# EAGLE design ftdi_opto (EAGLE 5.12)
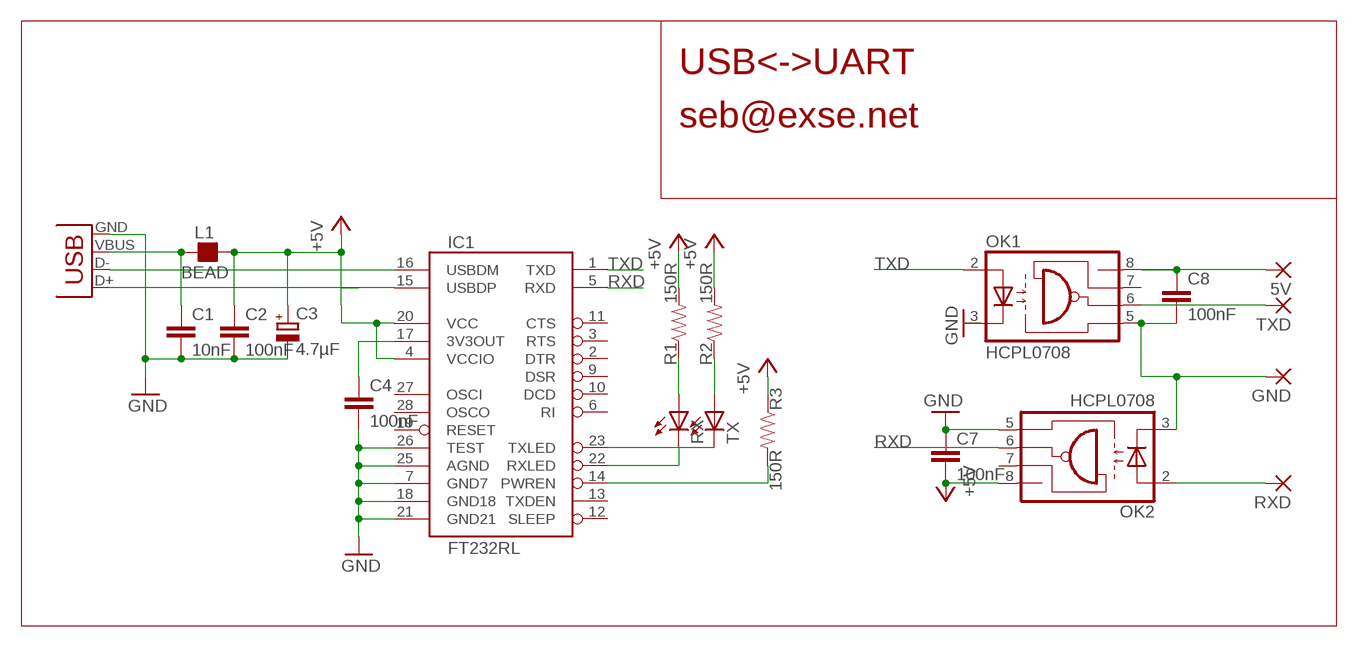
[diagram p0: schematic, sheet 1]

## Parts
5V  SMD2  [SMD1,27-2,54]
C1  10nF  CAP0805  [0805]
C2  100nF  CAP0805  [0805]
C3  4.7µF  CPOL-EUSMCC  [SMC_C]
C4  100nF  CAP0805  [0805]
C7  100nF  CAP0805  [0805]
C8  100nF  CAP0805  [0805]
GND  SMD2  [SMD1,27-2,54]
IC1  FT232RL  FT232RLSSOP  [SSOP28DB]
L1  BEAD  FB_0805  [L0805]
OK1  HCPL0708  HCPL0601  [SOIC08]
OK2  HCPL0708  HCPL0601  [SOIC08]
R1  150R  RESISTOR  [0805]
R2  150R  RESISTOR  [0805]
R3  150R  RESISTOR  [0805]
RX  LEDCHIP-LED0805  [CHIP-LED0805]
RXD  SMD2  [SMD1,27-2,54]
TX  LEDCHIP-LED0805  [CHIP-LED0805]
TXD  SMD2  [SMD1,27-2,54]
X1  USB-SMD-NS  [USB-MINIB-NOSTOP]

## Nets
+5V: C2.1 C3.+ C7.2 IC1.4(VCCIO) IC1.20(VCC) L1.2 OK2.8(VCC) R1.2 R2.2 R3.1
GND: C1.2 C2.2 C3.- C4.2 C7.1 IC1.7(GND7) IC1.18(GND18) IC1.21(GND21) IC1.25(AGND) IC1.26(TEST) OK1.3(C) OK2.5(GND) X1.GND
N$1: IC1.16(USBDM) X1.D-
N$2: IC1.15(USBDP) X1.D+
N$4: C1.1 L1.1 X1.VBUS
N$5: IC1.14(PWREN) R3.2
N$8: C8.2 GND.1(P) OK1.5(GND) OK2.3(C)
N$9: 5V.1(P) C8.1 OK1.8(VCC)
N$10: OK1.6(VO) TXD.1(P)
N$11: OK2.2(A) RXD.1(P)
N$19: R1.1 RX.A
N$20: R2.1 TX.A
N$27: IC1.22(RXLED) RX.C
N$28: IC1.23(TXLED) TX.C
N$29: C4.1 IC1.17(3V3OUT)
RXD: IC1.5(RXD) OK2.6(VO)
TXD: IC1.1(TXD) OK1.2(A)
Unconnected: IC1.2(DTR) IC1.3(RTS) IC1.6(RI) IC1.9(DSR) IC1.10(DCD) IC1.11(CTS) IC1.12(SLEEP) IC1.13(TXDEN) IC1.19(RESET) IC1.27(OSCI) IC1.28(OSCO) OK1.7(VE) OK2.7(VE)

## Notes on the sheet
- USB<->UART
- seb@exse.net

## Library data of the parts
5V GND RXD TXD = wirepad:SMD2: SMD PAD
C1 C2 C4 C7 C8 = SparkFun:CAP: Capacitor
C3 = resistor:CPOL-EU: POLARIZED CAPACITOR, European symbol
IC1 = SparkFun:FT232RL: USB UART FT232RL 4th Generation USB UART (USB <-> Serial) Controller. Spark Fun Electronics SKU : COM-00650
L1 = rc-master-smd:FB_: FERRITE BEAD
OK1 OK2 = optocoupler:HCPL0601: HEWLETT PACKARD OPTO COUPLER; MF: AGILENT TECHNOLOGIES; MPN: HCPL-0601-000E; OC_FARNELL: 9995102; OC_NEWARK: 88H7776
R1-R3 = SparkFun:RESISTOR: Resistor
RX TX = led:LED: LED
X1 = SparkFun:USB: USB Connectors USB-B-PTH is fully proven SKU : PRT-00139 USB-miniB is fully proven SKU : PRT-00587 USB-A-PCB is untested. USB-A-H is throughly reviewed, but untested. Spark Fun Electronics SKU : PRT-00437 USB-B-SMT is throughly reviewed, but untested. Needs silkscreen touching up. USB-A-S has not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

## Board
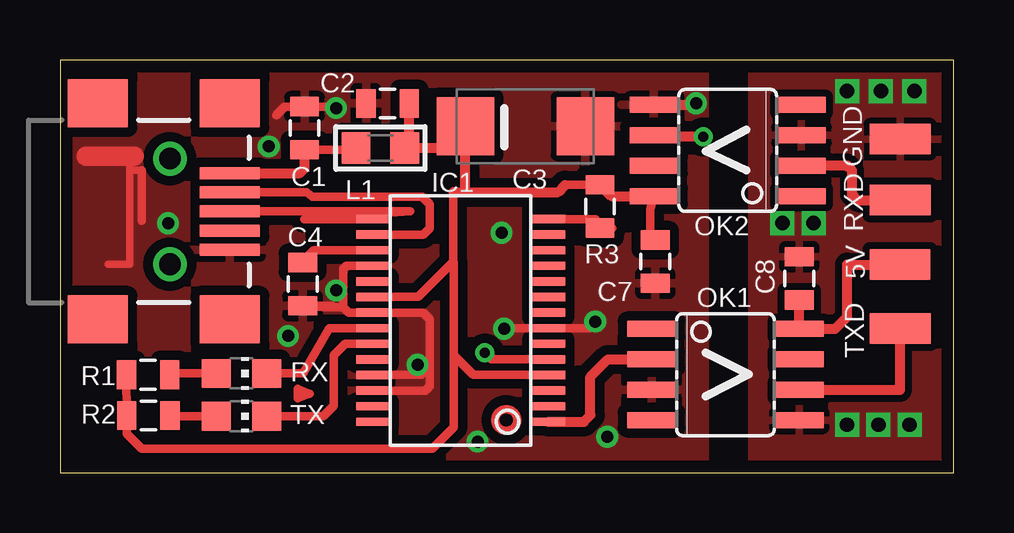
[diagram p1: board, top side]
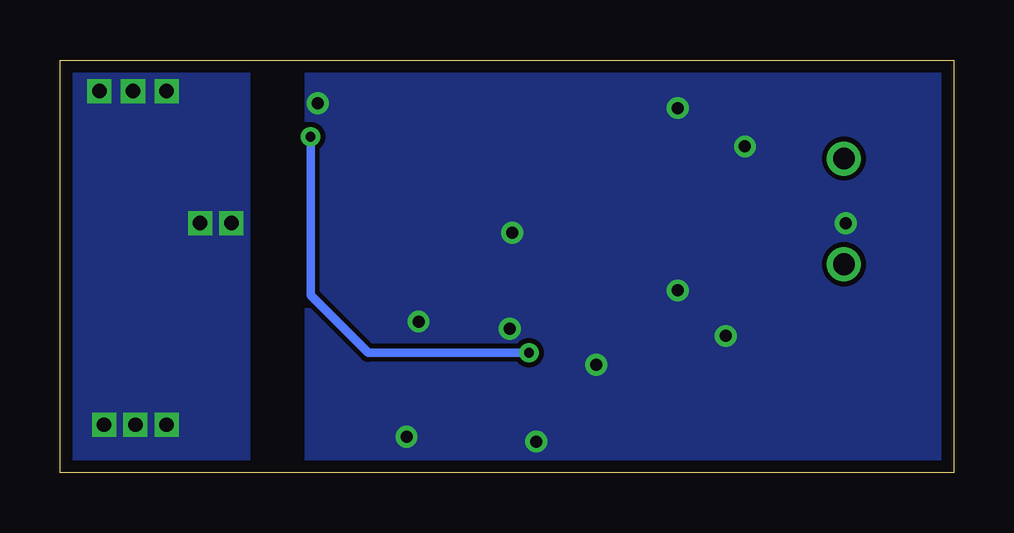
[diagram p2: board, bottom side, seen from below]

Size 37.24 x 17.2 mm. Coordinates in mm from the lower left corner, seen from the top.
Outline: 0,0 37.24,0 37.24,17.2 0,17.2 0,0
Copper layers (1*16): Top 0.035mm / dielectric 1.5mm / Bottom 0.035mm
Design rules "default *": minimum track width 10mil, minimum drill 0.3mm, track to track 8mil, track to pad 8mil, pad to pad 8mil, via to via 8mil, smd to smd 8mil, copper to edge 20mil, drill to drill 8mil, minimum pad ring 10mil, minimum via ring 8mil, stop-mask expansion 4mil, vias tented up to drill 50mil, thermal gap 10mil
tRestrict: 1 lines

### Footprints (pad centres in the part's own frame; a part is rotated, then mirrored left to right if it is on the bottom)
SMD1,27-2,54 = smd 1.27 x 2.54: 1 0,0
0805 = smd 0.8 x 1.2: 1 -0.9,0; 2 0.9,0
SMC_C = smd 2.4 x 2.4: + -2.5,0; - 2.5,0
SSOP28DB = smd 0.348 x 1.397: 1 -4.225,-3.656; 2 -3.575,-3.656; 3 -2.925,-3.656; 4 -2.275,-3.656; 5 -1.625,-3.656; 6 -0.975,-3.656; 7 -0.325,-3.656; 8 0.325,-3.656; 9 0.975,-3.656; 10 1.625,-3.656; 11 2.275,-3.656; 12 2.925,-3.656; 13 3.575,-3.656; 14 4.225,-3.656; 15 4.225,3.656; 16 3.575,3.656; 17 2.925,3.656; 18 2.275,3.656; 19 1.625,3.656; 20 0.975,3.656; 21 0.325,3.656; 22 -0.325,3.656; 23 -0.975,3.656; 24 -1.625,3.656; 25 -2.275,3.656; 26 -2.925,3.656; 27 -3.575,3.656; 28 -4.225,3.656
L0805 = smd 1.2 x 1.3: 1 -1.016,0; 2 1.016,0
SOIC08 = smd 0.66 x 2.032: 1 -1.905,-3.073; 2 -0.635,-3.073; 3 0.635,-3.073; 4 1.905,-3.073; 5 1.905,3.073; 6 0.635,3.073; 7 -0.635,3.073; 8 -1.905,3.073
CHIP-LED0805 = smd 1.2 x 1.2: A 0,-1.05; C 0,1.05
USB-MINIB-NOSTOP = smd 2.5 x 0.5: D+ 2.5,0; D- 2.5,0.8; GND 2.5,-1.6; ID 2.5,-0.8; VBUS 2.5,1.6 | smd 2.5 x 2: G1 -3,-4.5; G2 -3,4.5; G3 2.5,4.5; G4 2.5,-4.5 | drill 0.9 pad 0.8 round: H1 0,2.2 | drill 0.9 pad 0.787 round: H2 0,-2.2

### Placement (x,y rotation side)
5V  35,8.67 90 top
C1  10.19,14.36 90 top
C2  13.65,15.39 180 top
C3  19.39,14.44 0 top
C4  10.11,7.86 270 top
C7  24.8,8.8 90 top
C8  30.8,8.1 90 top
GND  35.01,13.9 90 top
IC1  16.69,6.35 90 top
L1  13.35,13.53 0 top
OK1  27.72,4.09 270 top
OK2  27.82,13.43 90 top
R1  3.67,4.09 180 top
R2  3.68,2.39 180 top
R3  22.5,11.1 270 top
RX  7.56,4.14 270 top
RXD  35,11.36 90 top
TX  7.56,2.36 270 top
TXD  35,6.01 90 top
X1  4.58,10.89 0 top

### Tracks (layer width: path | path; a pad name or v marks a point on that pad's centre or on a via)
+5V
  Top 0.35: IC1.20 14.93,7.33 16.39,8.79 | R1.2 R2.2 2.78,1.62 3.4,1 15.5,1 16.4,1.9 | 16.4,1.9 16.39,1.91 | 16.39,8.79 16.39,11.7 | 21.05,12 R3.1 | IC1.4 17.23,4.08 16.4,4.9 | 16.4,4.9 16.4,8.78 16.39,8.79 | 16.4,1.9 16.4,4.9 | OK2.8 24.6,10.98 24.6,9.9 24.6,9.7 C7.2
  Top 0.406: 21.05,12 20.75,11.7 16.9,11.7 | 16.39,11.7 16.9,11.7 | OK2.8 22.97,11.53 R3.1 | C2.1 14.55,13.71 L1.2 16.89,13.53 | 16.89,13.53 C3.+ | 16.89,13.53 16.89,11.7 16.9,11.7
GND  (via drill 0.5)
  Top 0.305: 2.9,12.6 3.4,12.6 | 2.9,12.6 2.9,13.2 | 2,8.7 2.9,8.7 2.9,12.6
  Top 0.35: IC1.26 15.22,3.43 15.4,3.6 15.4,4.4 | 15.4,4.4 15.4,6.4 15.12,6.68 IC1.21 12.03,6.68 11.8,6.9 | IC1.25 15.07,4.08 15.4,4.4 | 11.8,6.9 11.8,8.5 11.93,8.62 IC1.18 | 11.8,6.9 10.97,6.9 C4.2 11.34,6.96 | 11.36,15.26 C1.2 9.36,15.26 9,14.9 | 3.4,12.6 3.4,10.5 | 20.23,6.03 18.52,6.03 v18.5,6 | 20.23,6.03 IC1.7 | 20.23,6.03 22.05,6.03
  Top 0.406: OK2.5 26.34,15.34 v26.5,15.4
  Top 0.813: 1.1,13.2 2.9,13.2 3.1,13.2
  other vias: 9.5,5.7 11.5,7.6 14.9,4.5 18.4,10 11.5,15.2 8.7,13.6 4.5,10.4 22.8,1.5 22.3,6.3 17.4,1.3
  pour Top (isolate 0.4): 0,0 26.86,0.2 26.86,17.4 0,17.2
  pour Bottom: 26.88,17.4 0,17.2 0,0 26.88,0.2
N$1
  Top 0.35: IC1.16 15.12,9.93 15.4,10.2 15.4,11.2 15.1,11.5 10.5,11.5 10.29,11.69 X1.D-
N$2
  Top 0.35: X1.D+ 14.59,10.89 10.18,10.57 IC1.15
N$3
  Top 0.35: 9.9,3.5 9.9,3.1 10.4,3.3 9.9,3.5
N$4
  Top 0.35: C1.1 12.36,13.46 L1.1
  Top 0.406: X1.VBUS 9.99,12.49 10.19,12.69 C1.1 | L1.1 12.33,13.43
N$5
  Top 0.35: IC1.14 22.32,10.57 R3.2 23,10.2
N$8  (via drill 0.6)
  other vias: 30.1,10.4 31.4,10.4 34.1,2 34.2,15.9 32.8,2 35.4,2 32.8,15.9 35.6,15.9
  pour Bottom: 29.53,0.23 37.45,0.03 37.45,17.3 29.53,17.5
  pour Top (isolate 0.3): 28.83,0.03 37.45,0.03 37.45,17.3 28.83,17.3
N$9
  Top 0.35: OK1.8
  Top 0.406: OK1.8 C8.1 | 5V.1 32.8,8.67 32.8,6.5 32.3,6 OK1.8
N$10
  Top 0.406: TXD.1 35,3.46 OK1.6
N$11
  Top 0.406: OK2.2 32.8,12.8 33,12.6 33,11.6 33.24,11.36 RXD.1
N$19
  Top 0.35: R1.1 4.72,4.14 RX.A
N$20
  Top 0.35: R2.1 4.71,2.36 TX.A
N$27
  Top 0.35: RX.C 10.14,4.14 11.22,6.03 IC1.22
N$28
  Top 0.35: IC1.23 11.88,5.38 11.4,4.9 11.4,2.8 10.96,2.36 TX.C
N$29
  Top 0.35: C4.1 10.06,8.76 10.57,9.28 IC1.17
RXD  (via drill 0.4)
  Top 0.35: IC1.5 17.98,4.73 v17.7,5
  Top 0.406: v26.8,14 24.82,14 OK2.6
  Bottom 0.35: v17.7,5 24.4,5 26.8,7.4 v26.8,14
TXD
  Top 0.406: IC1.1 21.82,2.12 22.1,2.4 22.1,4 22.83,4.73 OK1.2
(copper drawn outside any net)
  shapes: Top circle x1

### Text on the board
bStop: GND | seb@exse.net | RX | 5V | TX | UART <-> USB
